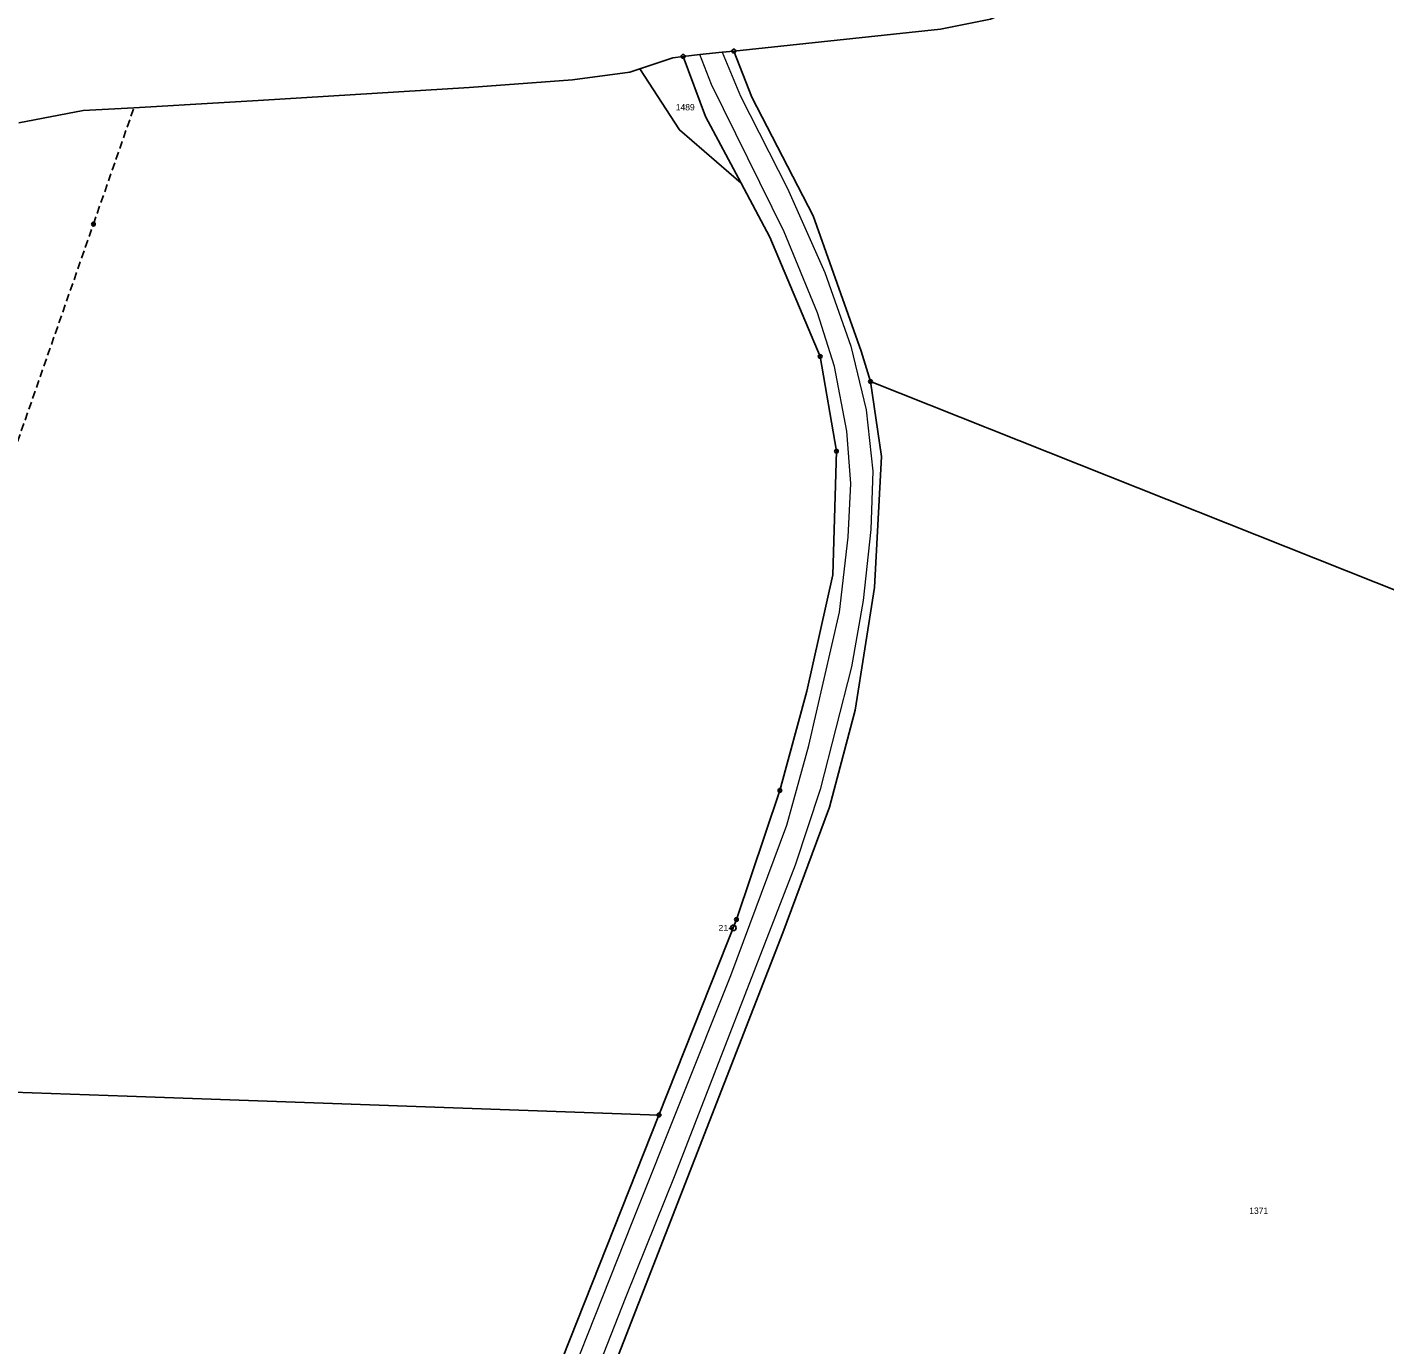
# Model space of a CAD drawing. Extents: x -872229 to -869198, y -1075981 to -1074329.
# Drawn here: x -871207 to -870843.3, y -1074936.4 to -1074583.6 of the extents above; entities that cross this region are included whole.
import ezdxf
from ezdxf.enums import TextEntityAlignment as Align

# ---------------------------------------------------------------- set-up
doc = ezdxf.new("R2010")
doc.units = 0
doc.header["$LTSCALE"] = 0.68
doc.linetypes.add('MEDIUM_DASHED', pattern=[4.5, 3, -1.5])
for name, color, linetype, lineweight in [('1', 7, 'Continuous', 25), ('4', 7, 'Continuous', 13), ('6', 7, 'Continuous', 25), ('8', 7, 'Continuous', 25)]:
    doc.layers.add(name, color=color, linetype=linetype, lineweight=lineweight)
doc.layers.add('2', color=7, linetype='Continuous')

msp = doc.modelspace()

# ---------------------------------------------------------------- linework, layer by layer
at = {"layer": '1'}
for points in [[(-870848.41, -1074534.87), (-870883.9, -1074554.93), (-870908.43, -1074563.86), (-870934.77, -1074575.4), (-870948.95, -1074581.46), (-870962.37, -1074584.16), (-871017.7, -1074589.98)], [(-871017.7, -1074589.98), (-871020.82, -1074590.31), (-871026.85, -1074590.94), (-871031.28, -1074591.41)], [(-871017.7, -1074589.98), (-871012.91, -1074602.34), (-870996.45, -1074634.07), (-870983.56, -1074670.35), (-870981.09, -1074678.49)], [(-871031.28, -1074591.41), (-871034.01, -1074591.76), (-871042.88, -1074594.72)], [(-871015.72, -1074625.4), (-871025.25, -1074607.47), (-871031.28, -1074591.41)], [(-871042.88, -1074594.72), (-871045.55, -1074595.6), (-871060.96, -1074597.73), (-871088.61, -1074599.78), (-871145.12, -1074603.23), (-871154.19, -1074603.78), (-871178.39, -1074605.16), (-871192.01, -1074605.93), (-871209.25, -1074609.21)], [(-871015.72, -1074625.4), (-871032.24, -1074611.11), (-871042.88, -1074594.72)], [(-871037.76, -1074874.85), (-871017, -1074822.52), (-871005.37, -1074787.95), (-870998.12, -1074761.36), (-870991.22, -1074730.22), (-870990.23, -1074697.13), (-870994.58, -1074671.74), (-871008.06, -1074639.82), (-871015.72, -1074625.4)], [(-870981.09, -1074678.49), (-870978.14, -1074698.51), (-870980.02, -1074733.6), (-870985.23, -1074766.42), (-870992.05, -1074792.43), (-871004.56, -1074826.1), (-871074.68, -1075006.03), (-871079.84, -1075019.17), (-871088.25, -1075040.59), (-871096.99, -1075058.79)], [(-870634.05, -1074816.48), (-870806.04, -1074748.1), (-870981.09, -1074678.49)], [(-871282.11, -1074866.22), (-871180.17, -1074869.82), (-871037.76, -1074874.85)], [(-871098, -1075028.09), (-871087.54, -1075000.31), (-871037.76, -1074874.85)]]:
    msp.add_lwpolyline(points, dxfattribs=at)
at = {"layer": '4'}
for p, q in [((-871020.82, -1074590.31), (-871015.88, -1074602.08)), ((-871015.88, -1074602.08), (-871003.35, -1074626.81)), ((-870986.33, -1074668.97), (-870982.28, -1074686.06)), ((-870989.39, -1074740.24), (-870987.11, -1074720.18)), ((-870981.01, -1074718.09), (-870983.08, -1074737.12)), ((-871018.55, -1074837.46), (-871003.48, -1074797.23)), ((-871033.54, -1074890.96), (-871046.65, -1074923.52))]:
    msp.add_line(p, q, dxfattribs=at)
for points in [[(-870987.11, -1074720.18), (-870986.4, -1074705.78), (-870987.43, -1074691.78), (-870990.7, -1074674.48), (-870995.31, -1074660.1), (-871004.24, -1074638.38), (-871023.65, -1074598.94), (-871026.85, -1074590.94)], [(-871003.35, -1074626.81), (-870993.36, -1074649.29), (-870986.33, -1074668.97)], [(-870982.28, -1074686.06), (-870980.48, -1074702.5), (-870981.01, -1074718.09)], [(-870983.08, -1074737.12), (-870986.22, -1074754.84), (-870994.55, -1074787.7), (-871001.25, -1074808), (-871033.54, -1074890.96)], [(-871003.48, -1074797.23), (-870997.63, -1074775.93), (-870989.39, -1074740.24)], [(-871070.54, -1074968.25), (-871044.98, -1074903.65), (-871018.55, -1074837.46)], [(-871046.65, -1074923.52), (-871058.82, -1074954.4), (-871080.04, -1075008.93)]]:
    msp.add_lwpolyline(points, dxfattribs=at)
at = {"layer": '6', "linetype": 'MEDIUM_DASHED'}
msp.add_line((-871189.25, -1074636.33), (-871178.39, -1074605.16), dxfattribs=at)
msp.add_lwpolyline([(-871241.92, -1074787.06), (-871217.63, -1074717.67), (-871189.25, -1074636.33)], dxfattribs=at)
at = {"layer": '6'}
for radius in [0.5, 0.4, 0.3, 0.2, 0.1]:
    msp.add_circle((-871189.2534, -1074636.3299), radius, dxfattribs=at)
at = {"layer": '8'}
for centre, radius in [((-871017.7, -1074589.9799), 0.5), ((-871017.7, -1074589.9799), 0.0303), ((-871031.28, -1074591.4099), 0.5), ((-871031.28, -1074591.4099), 0.0303), ((-870994.58, -1074671.7399), 0.5), ((-870994.58, -1074671.7399), 0.0303), ((-870981.09, -1074678.4899), 0.5), ((-870981.09, -1074678.4899), 0.0303), ((-870990.23, -1074697.1299), 0.5), ((-870990.23, -1074697.1299), 0.0303), ((-871005.37, -1074787.9499), 0.5), ((-871005.37, -1074787.9499), 0.0303), ((-871017, -1074822.5199), 0.5), ((-871017, -1074822.5199), 0.0303), ((-871017.82, -1074824.7298), 0.75), ((-871017.82, -1074824.7298), 0.03), ((-871037.76, -1074874.8499), 0.5), ((-871037.76, -1074874.8499), 0.0303)]:
    msp.add_circle(centre, radius, dxfattribs=at)

# ---------------------------------------------------------------- texts
at = {"layer": '2'}
for s, p in [('1489', (-871033.25, -1074605.88)), ('1371', (-870879.64, -1074901.33))]:
    msp.add_text(s, height=1.7, dxfattribs=at).set_placement(p)
at = {"layer": '8', "width": 1.2}
msp.add_text('214', height=1.5, dxfattribs=at).set_placement((-871017.82, -1074825.48), align=Align.RIGHT)

doc.saveas('drawing.dxf')
